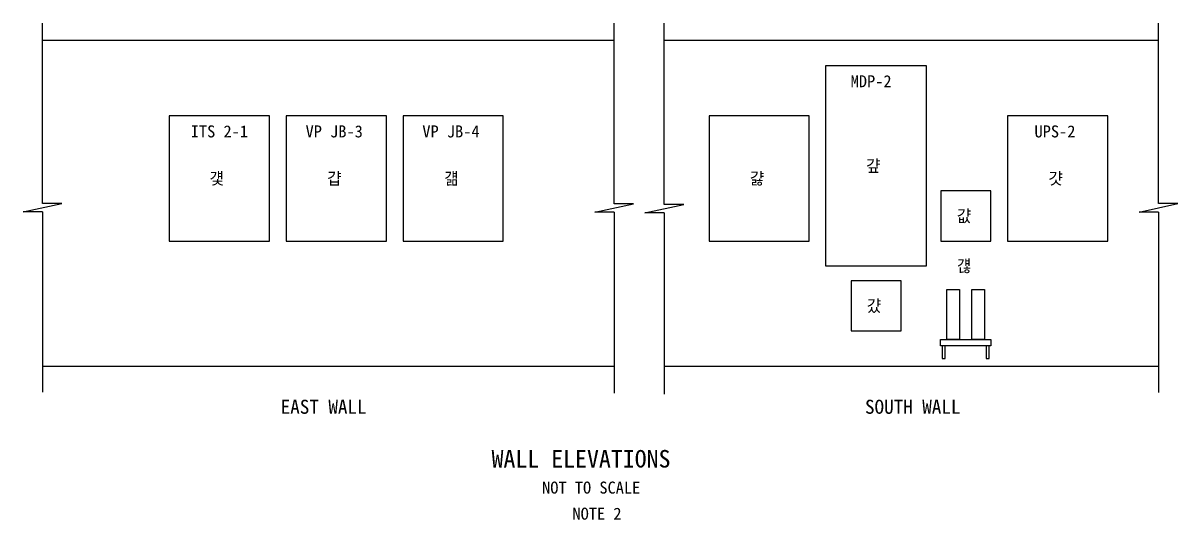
# Model space of a CAD drawing. Extents: x -0.4 to 22.7, y -3.1 to 6.8.
import ezdxf

# ---------------------------------------------------------------- set-up
doc = ezdxf.new("R2010")
doc.units = 0
for name, color, linetype in [('HS_Breakline_Straight_Line', 7, 'Continuous'), ('HS_Dimensions_and_Text', 7, 'Continuous'), ('HS_Electrical_Devices', 7, 'Continuous'), ('HS_Electrical_Enclosure', 7, 'Continuous'), ('HS_Miscellaneous', 7, 'Continuous')]:
    doc.layers.add(name, color=color, linetype=linetype)

msp = doc.modelspace()

# ---------------------------------------------------------------- linework, layer by layer
at = {"layer": 'HS_Breakline_Straight_Line'}
for p, q in [((0, 3.251), (0, 6.847)), ((11.41, 3.241), (11.41, 6.847)), ((12.41, 3.229), (12.41, 6.847)), ((22.273, 3.247), (22.273, 6.847)), ((-0.388, 3.085), (0.388, 3.251)), ((0.388, 3.251), (0, 3.251)), ((11.021, 3.074), (11.798, 3.241)), ((11.798, 3.241), (11.41, 3.241)), ((12.021, 3.063), (12.798, 3.229)), ((12.798, 3.229), (12.41, 3.229)), ((21.885, 3.08), (22.661, 3.247)), ((22.661, 3.247), (22.273, 3.247)), ((0, 3.085), (-0.388, 3.085)), ((0, 3.085), (0, -0.511)), ((11.41, 3.074), (11.021, 3.074)), ((11.41, 3.074), (11.41, -0.533)), ((12.41, 3.063), (12.021, 3.063)), ((12.41, 3.063), (12.41, -0.555)), ((22.273, 3.08), (21.885, 3.08)), ((22.273, 3.08), (22.273, -0.52))]:
    msp.add_line(p, q, dxfattribs=at)
at = {"layer": 'HS_Electrical_Devices'}
for points in [[(17.929, 2.5), (18.929, 2.5), (18.929, 3.5), (17.929, 3.5)], [(16.137, 0.709), (17.137, 0.709), (17.137, 1.709), (16.137, 1.709)], [(18.3, 0.537), (18.05, 0.537), (18.05, 1.537), (18.3, 1.537)], [(18.8, 0.537), (18.55, 0.537), (18.55, 1.537), (18.8, 1.537)], [(17.925, 0.537), (18.925, 0.537), (18.925, 0.412), (17.925, 0.412)], [(18.015, 0.412), (17.955, 0.412), (17.955, 0.162), (18.015, 0.162)], [(18.895, 0.412), (18.835, 0.412), (18.835, 0.162), (18.895, 0.162)]]:
    msp.add_lwpolyline(points, close=True, dxfattribs=at)
at = {"layer": 'HS_Electrical_Enclosure'}
for points in [[(15.637, 6), (17.637, 6), (17.637, 2), (15.637, 2)], [(2.53, 2.5), (4.53, 2.5), (4.53, 5), (2.53, 5)], [(4.864, 2.5), (6.864, 2.5), (6.864, 5), (4.864, 5)], [(7.197, 2.5), (9.197, 2.5), (9.197, 5), (7.197, 5)], [(13.304, 2.5), (15.304, 2.5), (15.304, 5), (13.304, 5)], [(19.262, 2.5), (21.262, 2.5), (21.262, 5), (19.262, 5)]]:
    msp.add_lwpolyline(points, close=True, dxfattribs=at)
at = {"layer": 'HS_Miscellaneous'}
for p, q in [((11.41, 6.5), (0, 6.5)), ((22.273, 6.5), (12.41, 6.5)), ((11.41, 0), (0, 0)), ((22.273, 0), (12.41, 0))]:
    msp.add_line(p, q, dxfattribs=at)

# ---------------------------------------------------------------- texts
at = {"layer": 'HS_Dimensions_and_Text'}
for s, height, p in [('MDP-2', 0.24, (16.13, 5.568)), ('ITS 2-1', 0.24, (2.958, 4.568)), ('VP JB-3', 0.24, (5.25, 4.568)), ('VP JB-4', 0.24, (7.58, 4.568)), ('UPS-2', 0.24, (19.799, 4.568)), ('걒', 0.24, (16.436, 3.88)), ('걫', 0.24, (3.332, 3.63)), ('걉', 0.24, (5.681, 3.63)), ('걞', 0.24, (8.017, 3.63)), ('걇', 0.24, (14.119, 3.63)), ('걋', 0.24, (20.078, 3.63)), ('걊', 0.24, (18.248, 2.88)), ('걚', 0.24, (18.249, 1.884)), ('걌', 0.24, (16.451, 1.089)), ('EAST WALL', 0.28, (4.753, -0.944)), ('SOUTH WALL', 0.28, (16.416, -0.944)), ('WALL ELEVATIONS', 0.35, (8.962, -2.016)), ('NOT TO SCALE ', 0.24, (9.971, -2.536)), ('NOTE 2', 0.24, (10.577, -3.056))]:
    msp.add_text(s, height=height, dxfattribs=at).set_placement(p)

doc.saveas('drawing.dxf')
